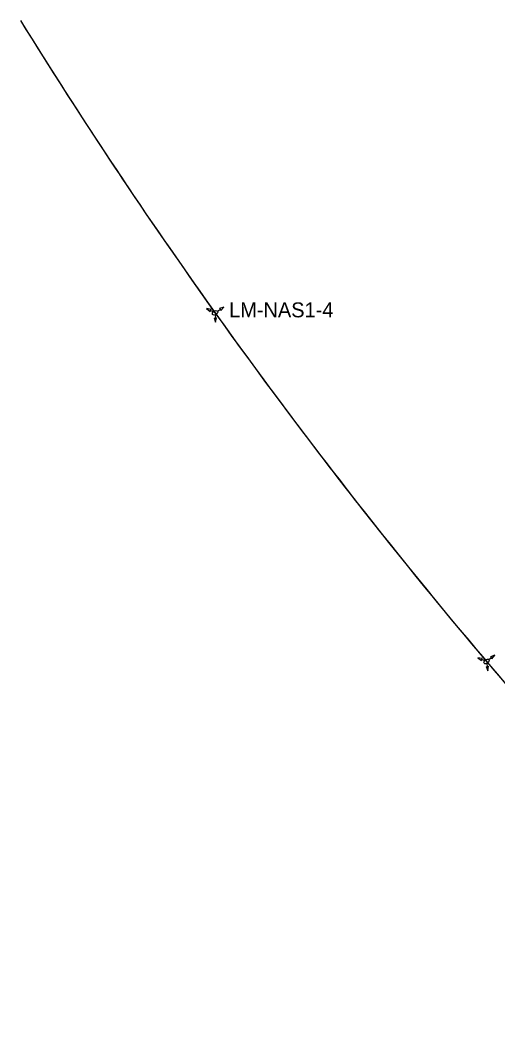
# Model space of a CAD drawing. Extents: x 1689971 to 1704302, y 703122 to 745602.
# Drawn here: x 1697956 to 1698211, y 718082 to 718629 of the extents above; entities that cross this region are included whole.
import ezdxf

# ---------------------------------------------------------------- set-up
doc = ezdxf.new("R2010")
doc.units = 0
for name, color, linetype in [('RD_X_Cells', 7, 'Continuous'), ('RD_X_Concrete_Barrier', 7, 'Continuous'), ('SV_X_Control_Cells_Found', 7, 'Continuous'), ('SV_X_Random_Point', 7, 'Continuous')]:
    doc.layers.add(name, color=color, linetype=linetype)

msp = doc.modelspace()

# ---------------------------------------------------------------- linework, layer by layer
at = {"layer": 'RD_X_Cells'}
for start, end in [(211.77598, 215.53886), (215.53886, 220.27606), (220.27606, 225.8689)]:
    msp.add_arc((1700391.04, 720137.92), 2864.79, start, end, dxfattribs=at)
at = {"layer": 'RD_X_Concrete_Barrier'}
for start, end in [(211.77598, 215.3689), (215.3689, 220.3689), (220.3689, 225.8689)]:
    msp.add_arc((1700391.04, 720137.92), 2864.79, start, end, dxfattribs=at)
at = {"layer": 'SV_X_Control_Cells_Found'}
for p, q in [((1698064.62, 718475.78), (1698062.26, 718475)), ((1698062.96, 718473.92), (1698064.62, 718475.78)), ((1698057.83, 718474.48), (1698055.39, 718474.99)), ((1698055.39, 718474.99), (1698057.25, 718473.33)), ((1698058.97, 718473.19), (1698057.36, 718474)), ((1698059.45, 718469.98), (1698060.23, 718467.62)), ((1698060, 718471.62), (1698060.11, 718469.82)), ((1698060.23, 718467.62), (1698060.74, 718470.06)), ((1698061.27, 718473.58), (1698062.78, 718474.57)), ((1698209.8, 718289.36), (1698207.51, 718288.39)), ((1698208.3, 718287.38), (1698209.8, 718289.36)), ((1698203.14, 718287.53), (1698200.67, 718287.84)), ((1698200.67, 718287.84), (1698202.65, 718286.34)), ((1698204.38, 718286.33), (1698202.71, 718287.01)), ((1698205.53, 718284.84), (1698205.78, 718283.06)), ((1698206.64, 718286.9), (1698208.07, 718288.01)), ((1698205.12, 718283.17), (1698206.08, 718280.88)), ((1698206.08, 718280.88), (1698206.39, 718283.35))]:
    msp.add_line(p, q, dxfattribs=at)
for centre, start, end in [((1698058.37, 718473.49), 118.7729, 187.8508), ((1698060.04, 718470.95), 238.7729, 307.8508), ((1698061.83, 718473.94), 358.7729, 67.8508), ((1698203.76, 718286.58), 123.3513, 192.4292), ((1698207.17, 718287.31), 3.3513, 72.4292), ((1698205.63, 718284.19), 243.3513, 312.4292)]:
    msp.add_arc(centre, 1.13, start, end, dxfattribs=at)
for centre, major_axis in [((1698059.94, 718472.7), (1.34, 0.88)), ((1698205.38, 718285.92), (1.26, 0.98))]:
    msp.add_ellipse(centre, major_axis=major_axis, ratio=0.625, dxfattribs=at)

# ---------------------------------------------------------------- texts
at = {"layer": 'SV_X_Random_Point'}
msp.add_text('LM-NAS1-4', height=8, dxfattribs=at).set_placement((1698067.46, 718470.27))

doc.saveas('drawing.dxf')
